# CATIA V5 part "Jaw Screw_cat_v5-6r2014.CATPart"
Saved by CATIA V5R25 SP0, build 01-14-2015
Part number: Jaw Screw
Material "Steel": density 7860 kg/m3, Young's modulus 2e+11 Pa, Poisson ratio 0.266, thermal expansion 1.17e-05 1/K
Bounding box of the stored display mesh (mm): x -9 to 9, y 0 to 138, z -8.948 to 8.97
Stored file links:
  C:\Users\Aidata\Desktop\Final Soru 1-Bench vice\Jaw Screw_cat_v5-6r2014.CATPart
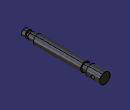
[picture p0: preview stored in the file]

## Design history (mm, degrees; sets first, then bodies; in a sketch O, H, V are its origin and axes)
Body1 (main body), material "Steel"
  Sketch1 on yz-plane, origin (0, 0, 0), H (0, 1, 0), V (0, 0, 1)
    line L1 (0, 0) -> (0, 6)
    line L2 (0, 6) -> (6, 6)
    line L3 (6, 6) -> (6, 4)
    line L4 (6, 4) -> (11, 4)
    line L5 (11, 4) -> (11, 6)
    point P5 (11, 6)
    line L6 (11, 6) -> (22, 6)
    line L7 (22, 6) -> (22, 8)
    line L8 (22, 8) -> (104, 8)
    line L9 (104, 8) -> (104, 6)
    point P9 (104, 6)
    line L10 (104, 6) -> (114, 6)
    line L11 (114, 6) -> (114, 9)
    line L12 (114, 9) -> (138, 9)
    line L13 (138, 9) -> (138, 0)
    point P13 (138, 0)
    line L14 (138, 0) -> (0, 0)
    distance L2 L14 = 6
    distance L8 L14 = 8
    distance L12 L14 = 9
    length L2 = 6
    length L4 = 5
    length L8 = 82
    length L10 = 10
    length L12 = 24
    length L14 = 138
    distance L4 L14 = 4
    vertical: L1 V, L3 V, L5 V, L7 V, L9 V, L11 V, L13 V
    horizontal: L2 H, L4 H, L6 H, L8 H, L10 H, L12 H, L14 H
    coincidence: P5 L2, P9 L6, P13 H
  Shaft1: profile Sketch1, axis edge of Sketch1, angle 360
  Sketch2 on yz-plane, origin (0, 0, 0), H (0, 1, 0), V (0, 0, 1)
    circle A1 centre (126, 0) radius 3
    point P1 (126, 0)
    radius A1 = 3
    distance P1 V = 126
    coincidence: P1 H
  Pocket1: profile Sketch2, direction (-1, 0, 0), length 20, mirrored extent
